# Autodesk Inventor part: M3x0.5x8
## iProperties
Company: 한국ATC센터
Created: 2009-02
Part Number: M3x0.5x8
Document SubType Name: Modeling
Designer: KYOUNG IL JANG
Density: 7.86 g/cm^3
Mass: 68.0563 g
Surface Area: 34.7349 cm^2
Volume: 8.65856 cm^3
Material: 강, 연강
Vendor: CBT Solutions
Author: KYOUNG IL JANG
